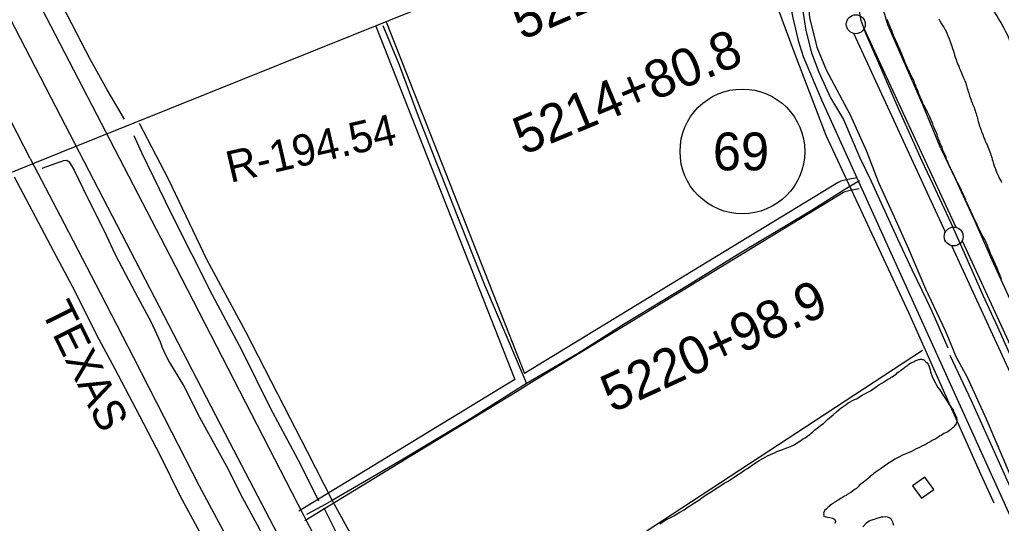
# Model space of a CAD drawing. Extents: x 3324125 to 3362000, y 600753 to 626151.
# Drawn here: x 3330131 to 3332729, y 614214 to 615545 of the extents above; entities that cross this region are included whole.
import ezdxf

# ---------------------------------------------------------------- set-up
doc = ezdxf.new("R2010")
doc.units = 0
for name, color, linetype in [('V-BLDG-OTLN', 7, 'Continuous'), ('V-BORW-LINE', 7, 'Continuous'), ('V-DTCH-CNTR', 7, 'Continuous'), ('V-FLOD-BASE', 7, 'Continuous'), ('V-LEVE-TOET', 7, 'Continuous'), ('V-RAIL-IDEN', 7, 'Continuous'), ('V-RAIL-TRAK', 7, 'Continuous'), ('V-RIVR-RANG-IDEN', 7, 'Continuous'), ('V-ROAD-CNTR', 7, 'Continuous'), ('V-ROAD-IDEN', 7, 'Continuous'), ('V-SITE-VEGE', 7, 'Continuous'), ('V-SURV-IDEN', 7, 'Continuous'), ('V-SURV-LINE', 7, 'Continuous'), ('V-TOPO-SHOR', 7, 'Continuous')]:
    doc.layers.add(name, color=color, linetype=linetype)

msp = doc.modelspace()

# ---------------------------------------------------------------- linework, layer by layer
at = {"layer": 'V-BLDG-OTLN'}
msp.add_lwpolyline([(3332549.7, 614303.2), (3332526.3, 614335.7), (3332493.8, 614312.4), (3332517.2, 614279.9)], close=True, dxfattribs=at)
at = {"layer": 'V-BORW-LINE'}
msp.add_spline([(3332917.4, 615371.8), (3332899, 615439.4), (3332887.3, 615494.3), (3332880.8, 615523.3), (3332845.9, 615674.6), (3332824, 615722.5), (3332777.6, 615836.6), (3332752.4, 615941.7), (3332736.3, 616052.4), (3332705.8, 616106.6), (3332674, 616103), (3332640.3, 616058.8), (3332622.6, 615934.4), (3332603.8, 615815.7), (3332645.4, 615673.5), (3332721.4, 615548), (3332760.5, 615451.5), (3332755.7, 615377.8), (3332775.8, 615229.9), (3332813.7, 615165), (3332893.3, 615037.2), (3332934.5, 614958.4), (3332934.6, 614916.2), (3332988.5, 614783.9), (3333008.6, 614752.7), (3333075.6, 614714.2), (3333096.8, 614723.6), (3333115.8, 614749.8), (3333132, 614783.4), (3333134.7, 614840.7), (3333127.6, 614881.8), (3333098, 614931.1), (3333018.3, 615080.4), (3332968.6, 615208.8), (3332941.7, 615292.2), (3332917.4, 615371.8)], degree=3, dxfattribs=at)
at = {"layer": 'V-DTCH-CNTR'}
for points in [[(3331091.4, 615529.9), (3331134.7, 615425.3), (3331184.9, 615289.7), (3331235.6, 615160.9), (3331299.1, 615000), (3331360.8, 614844.2), (3331424.9, 614693.6), (3331472.3, 614583)], [(3330447.3, 615271.4), (3330523.4, 615124.2), (3330626, 614910.4), (3330728.6, 614720.8), (3330830.1, 614523.1), (3330891.2, 614403.6), (3330957.7, 614274.3)], [(3332353.4, 615119.1), (3332319, 615099), (3332223.6, 615039), (3332032.8, 614924.9), (3331896, 614840.8), (3331733.4, 614741.6), (3331607, 614662.1), (3331472.3, 614583), (3331324, 614490.3), (3331145.9, 614383.6), (3330979.2, 614286.8), (3330957.7, 614274.3), (3330931.6, 614259.1), (3330889.3, 614236.7)], [(3330957.7, 614274.3), (3331010.7, 614177.8)]]:
    msp.add_lwpolyline(points, dxfattribs=at)
at = {"layer": 'V-FLOD-BASE'}
for points in [[(3332227.4, 616947.5), (3332230.4, 616875.1), (3332240.2, 616761.9), (3332252.8, 616641.6), (3332265.3, 616498.5), (3332282.8, 616307), (3332296.8, 616124.8), (3332307.5, 615977.1), (3332326, 615776.8), (3332341.5, 615636.1), (3332349.3, 615584.7), (3332355.5, 615546.7), (3332369.2, 615509.3), (3332410.1, 615416.8), (3332454.9, 615312.6), (3332517, 615173.9)], [(3332517, 615173.9), (3332547.1, 615109.8), (3332594.8, 615008.3), (3332633.7, 614920.9), (3332679.7, 614816.9), (3332718.6, 614732.7), (3332760.3, 614640.8), (3332814.8, 614525.5), (3332863.5, 614504.8), (3332899.2, 614465.7)]]:
    msp.add_lwpolyline(points, dxfattribs=at)
at = {"layer": 'V-LEVE-TOET'}
for points in [[(3332098.6, 616972.3), (3332097, 616912.8), (3332109.7, 616793), (3332125.4, 616612.6), (3332143.6, 616447.9), (3332162.1, 616232.5), (3332184.7, 616036.8), (3332201.7, 615777.6), (3332213.1, 615637.5), (3332221.3, 615551.1), (3332240, 615472.2), (3332264.7, 615412.5), (3332328.7, 615293.6), (3332371.9, 615197.6)], [(3332568.6, 615204.5), (3332520.9, 615319.8), (3332471.5, 615432.8), (3332428.3, 615531.7), (3332411.2, 615588.4)], [(3332371.9, 615197.6), (3332403.4, 615114.5), (3332445.1, 615023.5), (3332482.6, 614939), (3332527.5, 614833.9), (3332580.2, 614723.6), (3332599.7, 614676.8)], [(3332568.6, 615204.5), (3332607.1, 615123.1), (3332657.4, 615014.2), (3332703, 614910.3), (3332751.1, 614806)], [(3332599.7, 614676.8), (3332608.3, 614654.3), (3332638.3, 614600.3), (3332688.5, 614490), (3332751.9, 614341.1)]]:
    msp.add_lwpolyline(points, dxfattribs=at)
at = {"layer": 'V-RAIL-TRAK'}
for points in [[(3330158.4, 615178.1), (3330090.4, 615310)], [(3330158.4, 615178.1), (3330169.2, 615157.6), (3330248.2, 615006.4), (3330343.5, 614822.8), (3330431.7, 614651.9), (3330512.8, 614493.7), (3330605.3, 614312.9), (3330670.9, 614191.2)]]:
    msp.add_lwpolyline(points, dxfattribs=at)
at = {"layer": 'V-ROAD-CNTR'}
for points in [[(3328654.4, 618531.3), (3329365.9, 617157.1), (3329945, 616043.4), (3330528.3, 614922), (3330989.5, 614026.8), (3331101.4, 613813.5), (3331202.1, 613623.7), (3331288.2, 613468), (3331370, 613325.9), (3331489, 613122.4), (3331566.5, 612992.9), (3331683.8, 612804.9), (3331896.1, 612486.7), (3332030.8, 612296.1), (3332261.4, 611985.3), (3332414.1, 611792.3), (3332593.4, 611567.9), (3332751.8, 611383.2), (3332947.9, 611162.2), (3333176.2, 610911.4), (3333408.7, 610672.1), (3333754.4, 610344.1), (3333997.3, 610124.4), (3334416.3, 609777.9)], [(3328581.7, 618486.8), (3329049, 617590.5), (3329407, 616899.8), (3329876.9, 615987.8), (3330239, 615290.1), (3330685.5, 614428.5), (3331002.8, 613822.2), (3331099.5, 613638), (3331200, 613453.8), (3331306.4, 613261.3), (3331407.9, 613087), (3331494.8, 612942.7), (3331614.1, 612752.9), (3331713.9, 612602.5), (3331866.6, 612380.6), (3332016.4, 612177), (3332147.9, 611993.9), (3332265.1, 611843.6), (3332400.7, 611680.6), (3332500.3, 611558.3), (3332661.3, 611378.2), (3332840.8, 611178.7), (3333031, 610974.2)], [(3332050.3, 616945.8), (3332056, 616867), (3332083.1, 616527.3), (3332155.9, 615701.2), (3332162.6, 615620.8), (3332176.4, 615550.1), (3332191.1, 615490.1), (3332204, 615447.5), (3332252.4, 615333.1), (3332828.6, 614063.2)], [(3332062.8, 616703.3), (3331299.1, 616402.5), (3331283.7, 616393.5), (3331269.2, 616382.1), (3331260.5, 616370.6), (3331252.7, 616347.9), (3331246.8, 616320), (3331249.3, 616296.2), (3331258.3, 616256.3), (3331450.3, 615777.5), (3331453.2, 615748.7), (3331451.9, 615720), (3331443.3, 615699.2), (3331428.9, 615681.4), (3331411.3, 615667.7), (3331394.3, 615658.1), (3330239.3, 615193.5), (3328629.8, 614542.4), (3328220.6, 614377)], [(3331072.8, 615527.9), (3331441, 614593.8)], [(3331100.7, 615538.9), (3331467, 614609.6)], [(3332347.4, 615127.3), (3332321.9, 615122.8), (3332303.7, 615118.1), (3332296.5, 615114.4), (3331889.3, 614866.7)], [(3332352.6, 615097.7), (3332328.2, 615093.4), (3332314.4, 615089.9), (3332311.1, 615088.2), (3331906.7, 614842.1)], [(3331889.3, 614866.7), (3331467, 614609.6)], [(3331906.7, 614842.1), (3331485.6, 614585.9)], [(3331441, 614593.8), (3331174.8, 614431.8)], [(3331447.4, 614562.6), (3331184.5, 614402.6)], [(3331485.6, 614585.9), (3331447.4, 614562.6)], [(3331174.8, 614431.8), (3330869.7, 614246.2)], [(3331184.5, 614402.6), (3330885.3, 614220.5)]]:
    msp.add_lwpolyline(points, dxfattribs=at)
at = {"layer": 'V-ROAD-IDEN'}
msp.add_circle((3332043.2, 615196.7), 165, dxfattribs=at)
at = {"layer": 'V-SITE-VEGE'}
for points in [[(3332202.6, 614436.1), (3332209.8, 614439.7), (3332215.7, 614443.9), (3332224.1, 614451.1), (3332229.5, 614455.9), (3332235.4, 614460.7), (3332245, 614467.8), (3332250.9, 614473.2), (3332257.5, 614478), (3332268.8, 614488.2), (3332283.1, 614500.1), (3332292.7, 614508.5), (3332298.6, 614513.3), (3332304.6, 614518.7), (3332312.3, 614524.6), (3332317.7, 614528.2), (3332323.1, 614532.4), (3332338.6, 614540.2), (3332345.2, 614543.2), (3332360.1, 614552.2), (3332382.1, 614564.1), (3332394.7, 614573.1), (3332404.2, 614579.7), (3332413.7, 614585.1), (3332426.9, 614594), (3332434, 614597), (3332437, 614600), (3332440, 614601.2), (3332445.4, 614605.4), (3332450.1, 614608.4), (3332453.1, 614611.4), (3332459.7, 614616.2), (3332462.7, 614618.6), (3332467.4, 614621.6), (3332473.4, 614626.3), (3332478.2, 614629.9), (3332481.1, 614631.7), (3332484.1, 614634.1), (3332488.3, 614637.1), (3332491.3, 614638.9), (3332498.4, 614641.9), (3332500.2, 614643.1), (3332502.6, 614644.3), (3332507.4, 614645.5), (3332509.2, 614646.7), (3332511.6, 614646.7), (3332513.4, 614647.9), (3332516.9, 614647.9), (3332519.3, 614646.7), (3332521.7, 614646.7), (3332523.5, 614645.5), (3332527.7, 614641.9), (3332531.9, 614637.8), (3332534.9, 614634.2), (3332536.7, 614630), (3332540.3, 614619.3), (3332540.9, 614613.9), (3332545.7, 614601.4), (3332546.9, 614597.2), (3332553.4, 614585.8), (3332555.8, 614580.5), (3332560.6, 614572.7), (3332564.8, 614567.4), (3332568.4, 614562), (3332573.8, 614553), (3332579.2, 614545.3), (3332580.4, 614542.9), (3332587.5, 614532.2), (3332590.5, 614528), (3332595.3, 614522), (3332597.7, 614517.8), (3332600.7, 614513.7), (3332603.1, 614507.1), (3332605.5, 614503.5), (3332607.3, 614500), (3332608.5, 614495.8), (3332609.7, 614493.4), (3332610.9, 614487.4), (3332610.9, 614482), (3332609.1, 614477.3), (3332608.5, 614474.3), (3332604.9, 614471.3), (3332602.5, 614468.3), (3332599.6, 614465.9), (3332594.8, 614461.7), (3332591.2, 614458.7), (3332587, 614455.8), (3332581.1, 614452.8), (3332576.3, 614451), (3332569.7, 614446.2), (3332565, 614443.8), (3332560.2, 614440.2), (3332554.8, 614437.2), (3332545.9, 614433), (3332540.5, 614428.8), (3332534.5, 614426.4), (3332526.8, 614421.6), (3332520.2, 614418.7), (3332510.1, 614413.3), (3332503.5, 614410.3), (3332490.4, 614403.7)], [(3331825, 614212.4), (3331840.5, 614222.5), (3331851.3, 614227.9), (3331862, 614233.9), (3331877.5, 614243.5), (3331888.8, 614249.5), (3331899.6, 614257.2), (3331916.3, 614268), (3331927.6, 614275.2), (3331939.5, 614283.6), (3331954.5, 614293.1), (3331963.4, 614299.1), (3331971.8, 614304.5), (3331986.1, 614313.5), (3331995, 614319.5), (3332005.2, 614324.8), (3332018.9, 614333.8), (3332027.8, 614339.8), (3332036.2, 614345.8), (3332048.7, 614354.2), (3332057.1, 614358.9), (3332070.2, 614367.9), (3332088.1, 614379.9), (3332097, 614385.3), (3332109.5, 614392.4), (3332117.9, 614396), (3332128, 614400.2), (3332134.6, 614403.2), (3332150.7, 614409.2), (3332157.9, 614412.2), (3332166.2, 614414.6), (3332178.2, 614420), (3332185.3, 614424.8), (3332192.5, 614429), (3332202.6, 614436.1)], [(3332490.4, 614403.7), (3332480.3, 614399.5), (3332467.1, 614393.5), (3332457, 614388.7), (3332446.8, 614383.3), (3332443.3, 614380.9), (3332427.2, 614370.8), (3332421.8, 614366.6), (3332414.6, 614362.4)], [(3332414.6, 614362.4), (3332410.5, 614358.8), (3332400.3, 614351.6), (3332395, 614348), (3332391.4, 614345.1), (3332389.6, 614343.3), (3332387.2, 614342.1), (3332384.8, 614340.3), (3332382.4, 614339.1), (3332378.9, 614334.9), (3332375.9, 614332.5), (3332371.7, 614328.9), (3332352.6, 614313.4), (3332349.6, 614310.4), (3332344.9, 614306.2), (3332341.9, 614303.8), (3332334.7, 614299), (3332330.6, 614294.8), (3332326.4, 614293), (3332321, 614290), (3332318, 614287.6), (3332313.8, 614285.3), (3332308.5, 614281.7), (3332304.9, 614279.9), (3332301.3, 614277.5), (3332296.6, 614274.5), (3332293.6, 614273.3), (3332291.2, 614271.5), (3332288.2, 614269.7), (3332285.8, 614268.5), (3332284, 614267.3), (3332281, 614264.9), (3332278.7, 614263.7), (3332275.1, 614260.7), (3332272.7, 614258.3), (3332270.3, 614256.5), (3332264.9, 614251.2), (3332261.4, 614248.8), (3332260.2, 614246.4), (3332257.8, 614240.4), (3332258.4, 614238), (3332257.8, 614235.6), (3332259, 614232.6), (3332261.4, 614231.5), (3332263.8, 614230.9), (3332269.7, 614230.3), (3332275.1, 614229.1), (3332282.3, 614227.3), (3332287.7, 614223.7), (3332288.9, 614221.9), (3332289.5, 614217.8), (3332288.3, 614213.6)], [(3332361.7, 614204.7), (3332371.8, 614214.9), (3332379, 614220.3), (3332383.2, 614222.1), (3332393.3, 614225.1), (3332397.5, 614226.9), (3332411.8, 614231.1), (3332415.4, 614231.1), (3332422, 614231.7), (3332426.2, 614231.1), (3332433.3, 614228.1), (3332435.7, 614226.3), (3332437.5, 614223.3), (3332440.5, 614218), (3332441.7, 614213.8), (3332443.5, 614209)]]:
    msp.add_lwpolyline(points, dxfattribs=at)
at = {"layer": 'V-SURV-LINE'}
for points in [[(3332580.5, 614983.7), (3332338.1, 615508.5)], [(3332365.3, 615521.1), (3332607.8, 614996.3)], [(3332624.5, 614960), (3333033.4, 614073.8)], [(3333006.2, 614061.3), (3332597.3, 614947.5)]]:
    msp.add_lwpolyline(points, dxfattribs=at)
for centre in [(3332343.3, 615532.9), (3332602.5, 614971.9)]:
    msp.add_circle(centre, 25, dxfattribs=at)
at = {"layer": 'V-TOPO-SHOR'}
for p, q in [((3330238.3, 615169.6), (3330189.4, 615151.8)), ((3332544.8, 614774.9), (3332587.2, 614677.5)), ((3331527.7, 614022.3), (3332519.7, 614671.7))]:
    msp.add_line(p, q, dxfattribs=at)
for points in [[(3332079.8, 617015.2), (3332079.2, 616924), (3332083.6, 616853.8), (3332095.6, 616737.5), (3332102.8, 616629.9), (3332115.3, 616517.9), (3332127.6, 616387.6), (3332144.3, 616212.6), (3332159.4, 616070), (3332174.3, 615861.2), (3332184.7, 615740.4), (3332198.2, 615602.9), (3332211.5, 615516.4), (3332226.3, 615457), (3332245.5, 615405.9), (3332276.9, 615338.4), (3332310.8, 615281.2), (3332354.3, 615179.4)], [(3332049.3, 616645.5), (3332100.4, 616001.2), (3332105.5, 615873.4), (3332126, 615694.4), (3332136.2, 615576.8), (3332182.2, 615454.1), (3332264.1, 615239.3), (3332483.9, 614768.9), (3332673.1, 614344.5), (3332708.9, 614267.7)], [(3330407.7, 615281.7), (3330361.9, 615359.3), (3330318.2, 615438.9), (3330243.8, 615581.2)], [(3332571.8, 615208.1), (3332569.8, 615210.5), (3332568.7, 615213.7), (3332567.1, 615218.1), (3332565.9, 615221.3), (3332564.4, 615225.3), (3332562.4, 615229.3), (3332561.2, 615232.5), (3332560, 615236.4), (3332558.5, 615241.2), (3332556.9, 615245.6), (3332555, 615250), (3332553.4, 615253.2), (3332551.4, 615257.6), (3332550.2, 615261.2), (3332548.3, 615265.6), (3332547.1, 615269.2), (3332545.2, 615274), (3332544, 615276.8), (3332542.8, 615279.6), (3332540, 615285.2), (3332538.1, 615290), (3332536.9, 615293.2), (3332534.9, 615297.1), (3332533, 615300.3), (3332531, 615304.7), (3332529.4, 615307.9), (3332527.1, 615312.7), (3332524.3, 615317.9), (3332522, 615321.5), (3332520.4, 615325.5), (3332518.8, 615328.7), (3332516.9, 615334.3), (3332514.9, 615337.9), (3332513.7, 615341.1), (3332511.8, 615345.9), (3332510.6, 615348.7), (3332508.2, 615355.1), (3332506.7, 615359.9), (3332505.1, 615363.1), (3332503.5, 615367), (3332502.4, 615370.6), (3332500, 615375), (3332498.8, 615378.6), (3332497.3, 615383.8), (3332494.9, 615387.4), (3332492.5, 615392.2), (3332490.6, 615395.8), (3332488.2, 615401), (3332486.3, 615404.2), (3332484.3, 615409.8), (3332482.3, 615413.4), (3332480.8, 615416.6), (3332478.8, 615421.4), (3332476.8, 615425.4), (3332474.1, 615432.2), (3332472.9, 615435.3), (3332471.7, 615438.1), (3332470.6, 615440.9), (3332469, 615444.9), (3332467, 615449.7), (3332465.1, 615454.5), (3332462.7, 615459.7), (3332460.8, 615464.1), (3332459.6, 615466.9), (3332456.8, 615472.9), (3332455.6, 615475.7), (3332452.9, 615482.5), (3332450.5, 615487.3), (3332447.8, 615494.1), (3332446.2, 615497.2), (3332444.3, 615501.2), (3332442.3, 615506.8), (3332440.3, 615510.4), (3332438.4, 615516), (3332436.8, 615519.6), (3332435.6, 615523.2), (3332433.3, 615528.4), (3332431.7, 615532), (3332430.5, 615535.6), (3332428.2, 615541.2), (3332426.6, 615545.2)], [(3332563.2, 615547.1), (3332566, 615541.9), (3332570.3, 615534.3), (3332573.1, 615529.9), (3332576.2, 615525.5), (3332579.8, 615518.3), (3332582.5, 615513.5), (3332584.5, 615509.1), (3332586.9, 615502.7), (3332588.4, 615498.7), (3332590.4, 615494.3), (3332593.1, 615487.5), (3332594.7, 615482.4), (3332596.6, 615477.6), (3332599.4, 615469.2), (3332600.9, 615464), (3332602.5, 615458.8), (3332604.8, 615451.2), (3332606.4, 615446), (3332608.7, 615439.6), (3332610.3, 615435.7), (3332611.9, 615431.7), (3332613.8, 615426.1), (3332615.8, 615422.1), (3332617.4, 615418.1), (3332619.7, 615412.1), (3332621.3, 615407.7), (3332623.3, 615404.1), (3332624.8, 615399.3), (3332626.4, 615396.1), (3332628, 615392.9), (3332629.1, 615389.3), (3332631.1, 615385.7), (3332632.3, 615382.1), (3332633.5, 615379.4), (3332636.6, 615371.4), (3332637.4, 615367.8), (3332638.5, 615364.2), (3332639.7, 615359), (3332640.9, 615355), (3332642.4, 615350.6), (3332644.4, 615343.4), (3332645.9, 615339), (3332647.5, 615335.1), (3332649.9, 615329.1), (3332651, 615325.5), (3332652.6, 615321.5), (3332654.9, 615316.3), (3332656.5, 615312.7), (3332657.3, 615309.1), (3332659.2, 615303.9), (3332660.4, 615300.3), (3332661.6, 615297.1), (3332663.2, 615291.9), (3332664.3, 615288.3), (3332665.1, 615284.8), (3332666.7, 615279.6), (3332667.4, 615276), (3332668.2, 615272.8), (3332670.2, 615267.6), (3332670.9, 615263.6), (3332672.5, 615260), (3332674.9, 615253.2), (3332676.4, 615248.8), (3332679.2, 615242.1), (3332680.7, 615237.7), (3332682.3, 615233.3), (3332684.6, 615227.7), (3332685.8, 615224.1), (3332689.4, 615216.9), (3332690.9, 615214.1)], [(3330922.7, 614272), (3330873.5, 614370.1), (3330794.3, 614517.8), (3330719.8, 614669.6), (3330641.3, 614816.7), (3330532.7, 615031.8), (3330454.1, 615193.2), (3330433.6, 615238.1)], [(3332690.9, 615214.1), (3332692.1, 615211.3), (3332694.1, 615206.5), (3332694.6, 615205.2)], [(3332664.2, 615004.2), (3332662.5, 615007.4), (3332660, 615012.7), (3332658.2, 615015.8), (3332656.8, 615018.6), (3332654.7, 615024.3), (3332652.9, 615027.5), (3332651.5, 615031), (3332649.4, 615035.2), (3332648, 615038.4), (3332646.6, 615041.5), (3332644.4, 615046.5), (3332642.7, 615050.4), (3332640.9, 615054.2), (3332638.4, 615059.9), (3332635.9, 615064.1), (3332634.2, 615068.3), (3332631.7, 615075), (3332629.6, 615079.3), (3332626.8, 615086.3), (3332624.3, 615091.2), (3332622.2, 615095.8), (3332619, 615102.9), (3332616.9, 615107.1), (3332614, 615111.7), (3332611.2, 615117), (3332609.8, 615120.5), (3332608, 615123.3), (3332606.2, 615127.9), (3332603.4, 615133.2), (3332601.6, 615137.8), (3332600.2, 615140.9), (3332598.5, 615144.1), (3332596, 615149), (3332594.2, 615152.2), (3332592.8, 615155.4), (3332590.3, 615160.3), (3332588.9, 615163.8), (3332587.5, 615167), (3332585.7, 615171.2), (3332584.7, 615174), (3332582.2, 615180.4), (3332580.4, 615185), (3332578.7, 615189.6), (3332577.2, 615193.1), (3332575.8, 615196.3), (3332574.1, 615199.8), (3332573, 615203.3), (3332571.6, 615206.5), (3332571.8, 615208.1)], [(3332694.6, 615205.2), (3332696.8, 615200.3), (3332699.6, 615191.1), (3332701, 615187.6), (3332703.1, 615180.6), (3332704.6, 615175.6), (3332706, 615170.7), (3332706.7, 615167.2), (3332708.1, 615163.6), (3332709.5, 615158.7), (3332711.6, 615154.5), (3332713.1, 615150.9), (3332714.5, 615144.6), (3332716.6, 615140.4), (3332718, 615136.8), (3332720.8, 615131.2), (3332722.3, 615127.7), (3332724.4, 615123.5), (3332727.9, 615118.5), (3332729.3, 615115)], [(3330238.3, 615169.6), (3330246.8, 615172.4), (3330255.3, 615173.7), (3330261.3, 615169.6), (3330275.1, 615147), (3330309.2, 615075.5), (3330353.3, 614988.6), (3330383.3, 614924.4), (3330436, 614823.8), (3330479, 614745.8), (3330502.1, 614693.7), (3330507.4, 614678.3), (3330515.5, 614660.9), (3330527.2, 614639.1), (3330564.5, 614578.1), (3330606.7, 614494.5), (3330677.6, 614365.2), (3330720.6, 614281.2), (3330758.3, 614211.7), (3330776.9, 614176.5)], [(3332354.3, 615179.4), (3332383.7, 615117.7), (3332410.9, 615059.9), (3332454.1, 614965.8), (3332491.9, 614884.4), (3332530.4, 614804.1), (3332544.8, 614774.9)], [(3330652.3, 614106.8), (3330607.4, 614190.7), (3330555.6, 614286.6), (3330504.8, 614388.9), (3330447.5, 614498.4), (3330383.3, 614620.8), (3330335, 614710.7), (3330277.3, 614826.2), (3330221.3, 614932.3), (3330155.4, 615055.9), (3330116.6, 615129)], [(3332729.3, 614859), (3332727.9, 614862.5), (3332726.5, 614865.7), (3332725.4, 614868.5), (3332723.6, 614873.1), (3332722.2, 614875.9), (3332720.1, 614880.9), (3332719.1, 614884), (3332717.6, 614887.9), (3332714.8, 614893.9), (3332713, 614898.1), (3332711.3, 614902.7), (3332708.1, 614909.8), (3332706.3, 614914.3), (3332703.8, 614918.9), (3332700.3, 614927), (3332698.5, 614932), (3332696.4, 614936.5), (3332693.9, 614942.5), (3332692.5, 614946.8), (3332690, 614952), (3332688.6, 614955.9), (3332686.5, 614960.1), (3332683.3, 614966.8), (3332680.5, 614971.1), (3332678, 614974.9), (3332675.2, 614980.6), (3332673.8, 614983.8), (3332672.4, 614986.6), (3332670.2, 614990.5), (3332669.2, 614993.3), (3332665.3, 615000.7), (3332664.2, 615004.2)], [(3332592.6, 614657.8), (3332648.7, 614538.6), (3332736.1, 614344.6), (3332776.4, 614254), (3332800.3, 614195.5), (3332821.5, 614151.2), (3332850.2, 614089.3), (3332868, 614055.9), (3332896.7, 614001.4), (3332919.2, 613968.8), (3332934.9, 613947), (3332949.2, 613928.6), (3332977.9, 613900.7), (3333106.8, 613787.1), (3333222.7, 613687.8), (3333222.7, 613683)], [(3331854.7, 612684.6), (3331838.4, 612673.6), (3331836.3, 612674.3), (3331751, 612789.3), (3331652.7, 612945.9), (3331632.2, 612984.7), (3331598.8, 613031.7), (3331529.8, 613146.7), (3331476.5, 613244.1), (3331461.5, 613272), (3331434.9, 613313.5), (3331395.3, 613382.2), (3331364.6, 613438.8), (3331350.9, 613463.9), (3331317.5, 613516.4), (3331249.8, 613645.7), (3331183.6, 613768.2), (3331105.7, 613911.2), (3331033.3, 614056.9), (3330977.3, 614172.6), (3330936.3, 614253.7)]]:
    msp.add_lwpolyline(points, dxfattribs=at)

# ---------------------------------------------------------------- texts
at = {"layer": 'V-RAIL-IDEN'}
msp.add_text('TEXAS', height=83, rotation=296.2834, dxfattribs=at).set_placement((3330185.9, 614775.5))
at = {"layer": 'V-RIVR-RANG-IDEN'}
msp.add_text('R-194.54', height=83, rotation=13.0209, dxfattribs=at).set_placement((3330688, 615113.4))
at = {"layer": 'V-ROAD-IDEN'}
msp.add_text('69', height=100, rotation=359.9873, dxfattribs=at).set_placement((3331965.2, 615146.8))
at = {"layer": 'V-SURV-IDEN'}
for s, rotation, p in [('5210+86.9', 23.3725, (3331460, 615489.7)), ('5214+80.8', 22.5997, (3331463.6, 615186.2)), ('5220+98.9', 24.6897, (3331699, 614504.7))]:
    msp.add_text(s, height=100, rotation=rotation, dxfattribs=at).set_placement(p)

doc.saveas('drawing.dxf')
